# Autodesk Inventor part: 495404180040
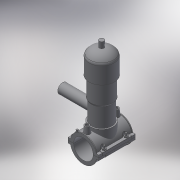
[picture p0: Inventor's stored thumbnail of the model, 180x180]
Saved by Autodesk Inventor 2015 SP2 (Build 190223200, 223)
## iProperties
Created: 2017-07
Part Number: 495404180040
Material: Generic
Description: PLASSON TAPPING VALVE 180-40
Document SubType Name: Modeling
Designer: KIM
Density: 1 g/cm^3
Appearance: Default
Author: KIM
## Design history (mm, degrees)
derived "495404-4954S4.ipt"
feature "Solid1::495404-4954S4.ipt"
feature "Solid2::495404-4954S4.ipt"
tag "TaggingFeature1"
body "Solid1"
body "Solid2"
other parameters: "d3" = 45, "d4" = 118, "d5" = 0, "d6" = 0.1, "d8" = 0, "d19" = 6, "d20" = 6, "d21" = 70.8, "d23" = 0, "d24" = 35.4, "d26" = 0, "d27" = 3, "d28" = 3, "d29" = 3, "d31" = 6, "d32" = 0, "d33" = 0, "d34" = 0.6, "d40" = 109.512, "d47" = 151.3, "d70" = 15, "d72" = 0, "d73" = 6, "d75" = 5, "d76" = 0, "d77" = 9, "d79" = 15, "d80" = 47.2, "d82" = 5 deg, "d84" = 4, "d85" = 14, "d86" = 0, "d87" = 3, "d88" = 0, "d89" = 1, "d90" = 1, "d91" = 94.4, "d92" = 0, "d93" = 0.5, "d94" = 94.73684, "d96" = 216.918, "d97" = 2.36, "d98" = 0, "d120" = 140 deg, "d121" = 24.228, "d122" = 20 deg, "d123" = 421.2, "d124" = 126.36, "d126" = 0, "d143" = 185.4, "d145" = 23.53846, "d149" = 2.7, "d150" = 25.89231, "d153" = 118, "d154" = 0, "d156" = 105.3, "d157" = 160 deg, "d159" = 6.12, "d161" = 2.7, "d162" = 70.8, "d163" = 0, "d167" = 18, "d168" = 102.73171, "d170" = 3, "d172" = 0, "d173" = 1, "d176" = 20 deg, "d177" = 12.6, "d178" = 30.6, "d180" = 0, "d183" = 12.24, "d184" = 10.08, "d185" = 38.35, "d186" = 38.35, "d187" = 105.3, "d188" = 9.18, "d189" = 12.6, "d190" = 0, "d191" = 157.95, "d193" = 6.8, "d194" = 2.95, "d195" = 90 deg, "d197" = 0, "d199" = 0, "d205" = 14.64, "d206" = 81.33333, "d207" = 244, "d208" = 224.48, "d209" = 207.4, "d210" = 200.08, "d211" = 146.4, "d212" = 85.4, "d213" = 65.88, "d214" = 73.2, "d216" = 19.52, "d217" = 70.76, "d218" = 80.52, "d222" = 0, "d223" = 210.6, "d224" = 137, "d225" = 46, "d229" = 137, "d230" = 0, "H_" = 137, "L_" = 118, "d_t" = 6, "H_1" = 46, "H_2" = 244, "d148" = 2.7, "d160" = 2.7, "d169" = 3, "d192" = 6.8, "d228" = 32
